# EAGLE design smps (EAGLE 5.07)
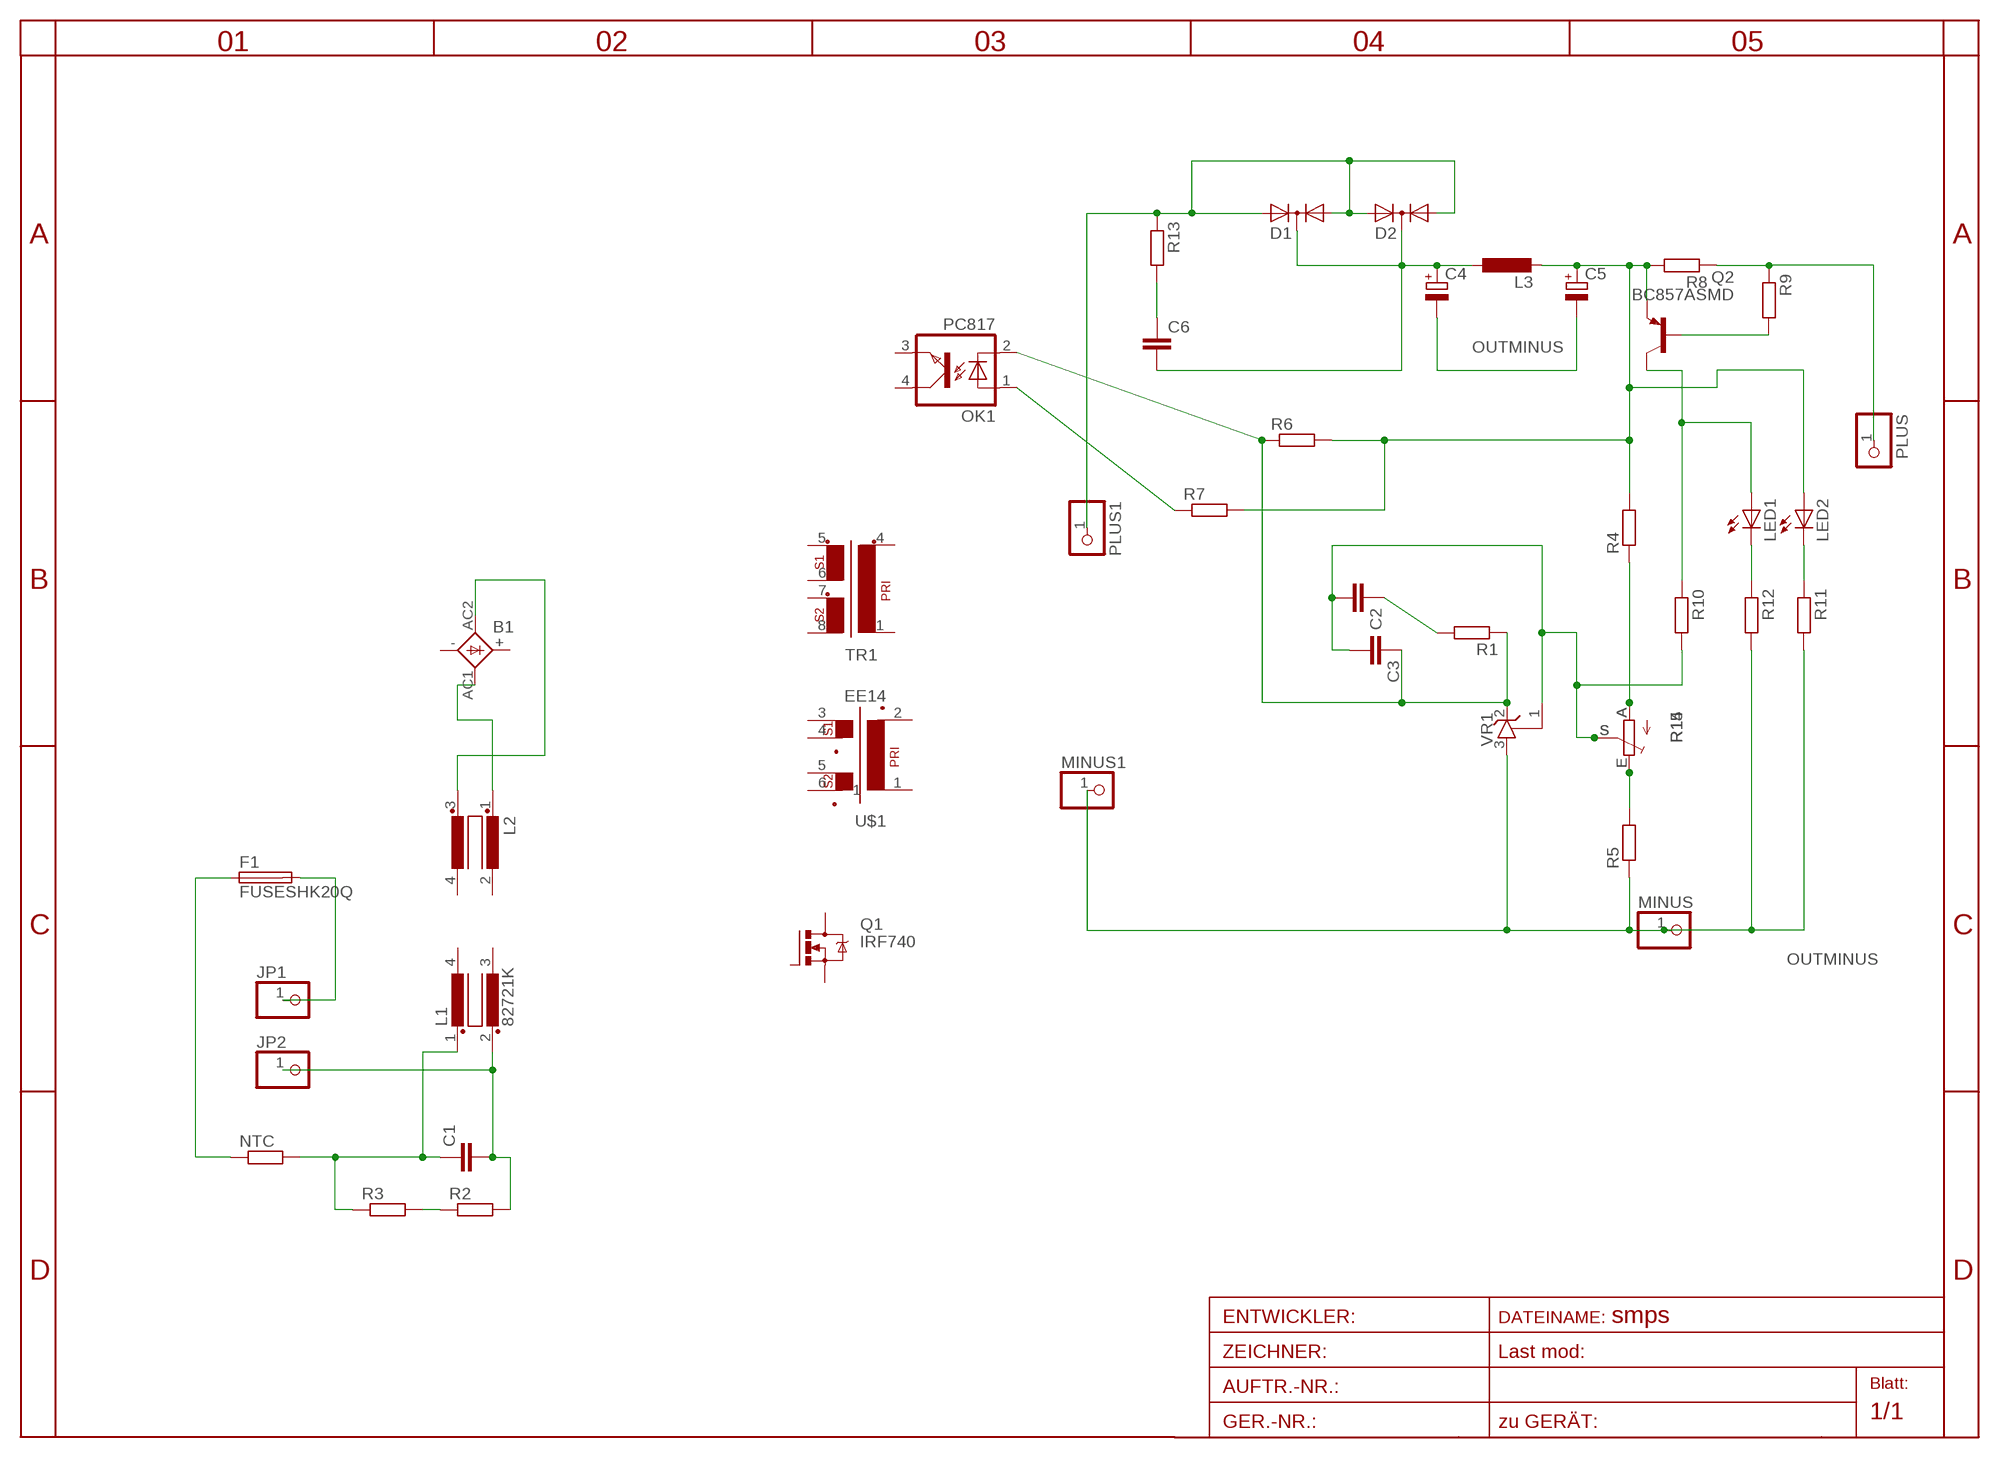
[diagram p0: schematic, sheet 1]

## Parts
B1  KBL  [KBL]
C1  C-EU150-084X183  [C150-084X183]
C2  C-EUC0805  [C0805]
C3  C-EUC0805  [C0805]
C4  CPOL-EUE5-8.5  [E5-8,5]
C5  CPOL-EUE5-8.5  [E5-8,5]
C6  C-EUC0805  [C0805]
D1  DIODE-2AC|CAIW220V  [IW220ABS]
D2  DIODE-2AC|CAIW220V  [IW220ABS]
F1  FUSESHK20Q  [SHK20Q]
JP1  PINHD-1X12MM2  [1X2MM2]
JP2  PINHD-1X12MM2  [1X2MM2]
L1  82721K  [82721K]
L2  R1405VB1  [B1]
L3  L-EU0204/5  [0204/5]
LED1  LED3MM  [LED3MM]
LED2  LED3MM  [LED3MM]
MINUS  PINHD-1X12MM2  [1X2MM2]
MINUS1  PINHD-1X11X0.4  [1X01]
NTC  R-EU_0204/7  [0204/7]
OK1  PC817  [DIL04]
PLUS  PINHD-1X12MM2  [1X2MM2]
PLUS1  PINHD-1X11X0.4  [1X01]
Q1  IRF740  [TO220BV]
Q2  BC857ASMD  [SOT23-BEC]
R1  R-EU_R0805  [R0805]
R2  R-EU_R1206  [R1206]
R3  R-EU_R1206  [R1206]
R4  R-EU_R0805  [R0805]
R5  R-EU_R0805  [R0805]
R6  R-EU_R0805  [R0805]
R7  R-EU_R0805  [R0805]
R8  R-EU_R2010  [R2010]
R9  R-EU_R0805  [R0805]
R10  R-EU_R0805  [R0805]
R11  R-EU_R0805  [R0805]
R12  R-EU_R0805  [R0805]
R13  R-EU_R0805  [R0805]
R14  TRIM_EU-S64W  [S64W]
R15  TRIM_EU-CA6V  [CA6V]
TR1  EE20-2  [EE20-2]
U$1  EE14  [EE14]
VR1  TL431CLPSOT23  [SOT23]

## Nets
A: R4.1 R14.A R15.A
CPLUS: C4.+ C6.2 D1.C D2.C L3.1
E: R5.2 R14.E R15.E
N$1: C1.2 JP2.1 L1.2 R2.2
N$2: C1.1 L1.1 NTC.2 R3.1
N$3: F1.2A JP1.1
N$6: R2.1 R3.2
N$7: B1.AC2(AC1) L2.3
N$8: B1.AC1(AC2) L2.1
N$9: F1.1A NTC.1
N$11: C3.1 OK1.2(C) R1.1 R6.1 VR1.2(C)
N$12: OK1.1(A) R7.1
N$13: C2.1 R1.2
N$14: D1.A1 D1.A2 D2.A1 D2.A2 PLUS1.1 R13.1
N$16: Q2.B R9.2
N$17: LED1.A Q2.C R10.1
N$21: LED1.K(C) R12.1
N$23: LED2.K(C) R11.1
N$27: C6.1 R13.2
OUTMINUS: C4.- C5.- MINUS1.1 MINUS.1 R5.1 R11.2 R12.2 VR1.3(A)
OUTPLUS: PLUS.1 R8.1 R9.1
PLUS2: C5.+ L3.2 LED2.A Q2.E R4.2 R6.2 R7.2 R8.2
S: C2.2 C3.2 R10.2 R14.S R15.S VR1.1(R)
Unconnected: B1.+ B1.- L1.3 L1.4 L2.2 L2.4 OK1.3(EMIT) OK1.4(COL) Q1.D Q1.G Q1.S TR1.1 TR1.4 TR1.5 TR1.6 TR1.7 TR1.8 U$1.1 U$1.2 U$1.3 U$1.4 U$1.5 U$1.6

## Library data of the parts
B1 = rectifier:KBL: DIOTEC RECTIFIER
C1-C3 C6 = rcl:C-EU: CAPACITOR, European symbol
C4 C5 = rcl:CPOL-EU: POLARIZED CAPACITOR, European symbol
D1 D2 = diode:DIODE-2AC|CA: Dual DIODE Anode-Cathode|Cathode-Anode
F1 = fuse:FUSE: Fuse
JP1 JP2 MINUS MINUS1 PLUS PLUS1 = pinhead:PINHD-1X1: PIN HEADER
L1 = inductors:82721K: FILTER
L2 = inductor-nkl:R1405V: Übertrager (verlustarm) bis typ. 400kHz Power transformer (low loss) up to typ. 400kHz
L3 = rcl:L-EU: INDUCTOR, European symbol
LED1 LED2 = led:LED: LED
NTC R1-R13 = rcl:R-EU_: RESISTOR, European symbol
OK1 = optocoupler:PC817: SHARP OPTO COUPLER
Q1 = transistor-power:IRF740: N-CHANNEL MOS FET
Q2 = transistor-pnp:BC857*: PNP Transistror
R14 R15 = pot:TRIM_EU-: POTENTIOMETER
TR1 = trafo:EE20-2: TRANSFORMER 1 primary winding, 2 secondary windings ERA
U$1 = trafo:EE14
VR1 = v-reg:TL431CLP: VOLTAGE REGULATOR

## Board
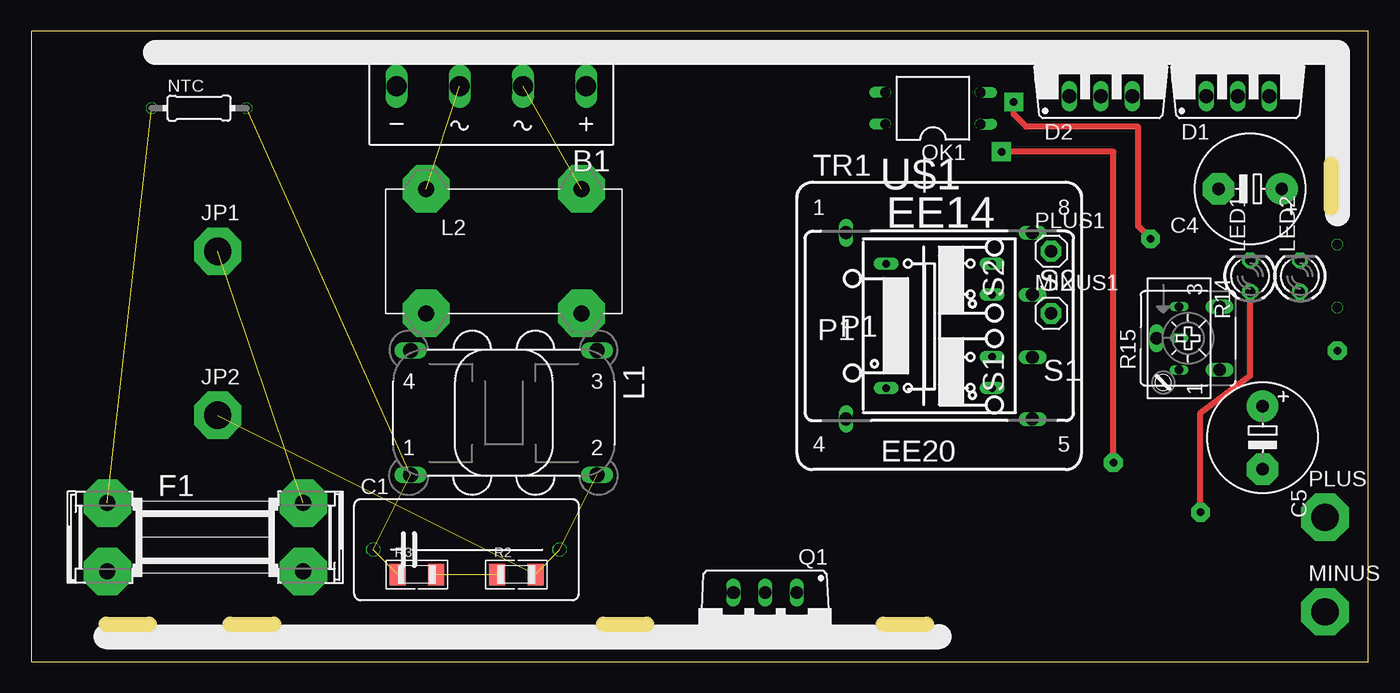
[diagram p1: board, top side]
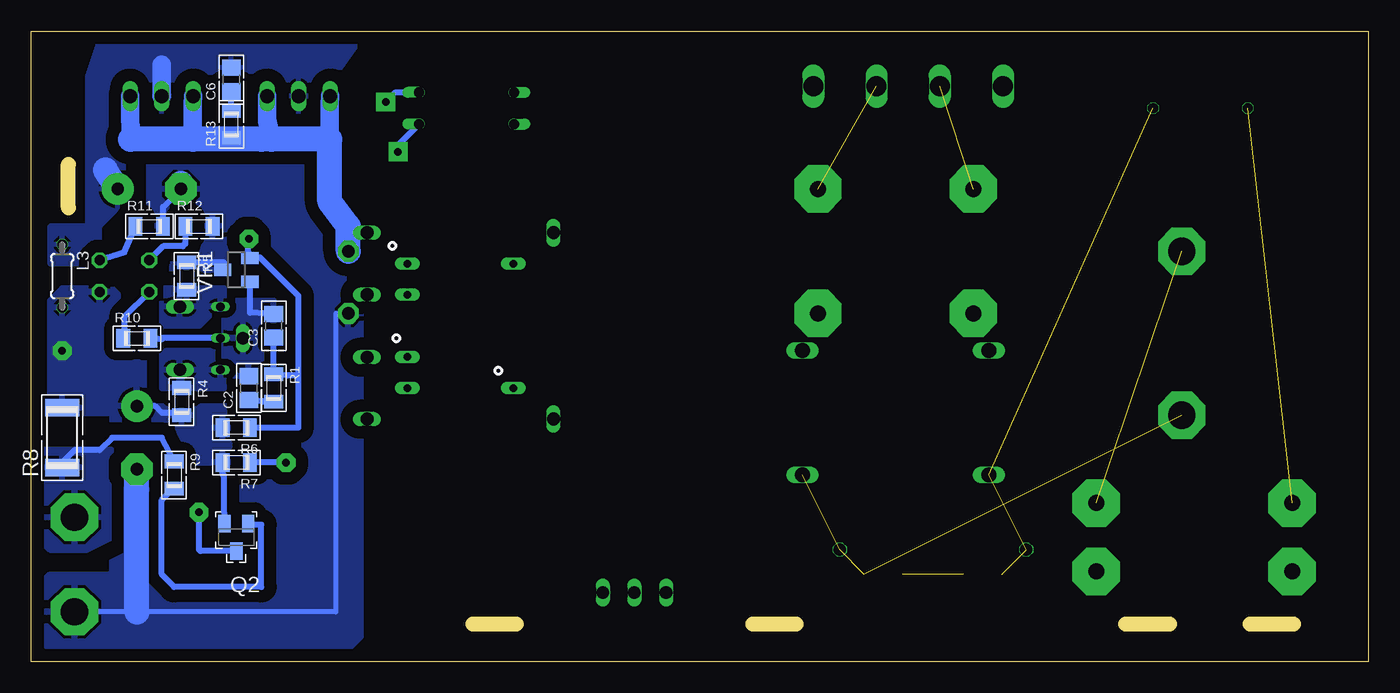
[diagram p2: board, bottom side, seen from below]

Size 107.5 x 50.7 mm. Coordinates in mm from the lower left corner, seen from the top.
Outline: 0,0 107.5,0 107.5,50.7 0,50.7 0,0
Copper layers (1*16): Top 0.035mm / dielectric 1.5mm / Bottom 0.035mm
Design rules "default": minimum track width 10mil, minimum drill 20mil, track to track 8mil, track to pad 8mil, pad to pad 8mil, via to via 8mil, smd to smd 8mil, copper to edge 40mil, drill to drill 8mil, minimum pad ring 1mil, minimum via ring 8mil, stop-mask expansion 4mil, vias tented up to drill 0mil, thermal gap 10mil
Milling: 5 lines

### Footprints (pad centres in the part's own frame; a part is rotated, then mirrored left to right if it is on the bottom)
KBL = drill 1.6 long: + -7.62,-1.27; - 7.62,-1.27; AC1 2.54,-1.27; AC2 -2.54,-1.27
C150-084X183 = drill 1.016 octagon: 1 -7.493,0; 2 7.493,0
C0805 = smd 1.3 x 1.5: 1 -0.95,0; 2 0.95,0
E5-8,5 = drill 1 pad 2.54 round: + -2.54,0 | drill 1 pad 2.54 octagon: - 2.54,0
IW220ABS = drill 1.118 long: A1 -2.54,-2.54; A2 2.54,-2.54; C 0,-2.54
SHK20Q = drill 1.3 pad 3.81 octagon: 1A -7.874,2.75; 1B -7.874,-2.75; 2A 7.874,2.75; 2B 7.874,-2.75
1X2MM2 = drill 2.2 pad 3.81 octagon: 1 0,0
82721K = drill 1.194 long: 1 7.493,5.004; 2 -7.493,5.004; 3 -7.493,-5.004; 4 7.493,-5.004
B1 = drill 1.27 pad 3.81 octagon: 1 -6.25,5; 2 -6.25,-5; 3 6.25,5; 4 6.25,-5
0204/5 = drill 0.813 octagon: 1 -2.54,0; 2 2.54,0
LED3MM = drill 0.8 pad 1.27 octagon: A -1.27,0; K 1.27,0
1X01 = drill 1 pad 1.676 octagon: 1 0,0
0204/7 = drill 0.813 octagon: 1 -3.81,0; 2 3.81,0
DIL04 = drill 0.813 offset: 1 -1.27,-3.81; 2 1.27,-3.81; 3 1.27,3.81; 4 -1.27,3.81
TO220BV = drill 1.016 long: D 0,-2.54; G -2.54,-2.54; S 2.54,-2.54
SOT23-BEC = smd 1 x 1.4: B -0.95,-1.1; C 0,1.1; E 0.95,-1.1
R0805 = smd 1.1 x 1.5: 1 -1.1,0; 2 1.1,0
R1206 = smd 1.3 x 1.7: 1 -1.55,0; 2 1.55,0
R2010 = smd 1.4 x 2.7: 1 -2.4,0; 2 2.4,0
S64W = drill 0.7 long: A 2.54,1.27; E -2.54,1.27; S 0,1.27
CA6V = drill 1.016 long: A -2.54,-2.54; E 2.54,-2.54; S 0,2.54
EE20-2 = drill 1.016 long: 1 -7.493,7.493; 4 -7.493,-7.493; 5 7.493,-7.493; 6 7.493,-2.515; 7 7.493,2.515; 8 7.493,7.493
EE14 = drill 0.6 pad 1 long: 1 4.25,-5; 2 4.25,5; 3 -4.25,5 | drill 0.6 pad 1.016 long: 4 -4.25,2.5; 5 -4.25,-2.5; 6 -4.25,-5
SOT23 = smd 1 x 1.4: 1 -0.95,-1.1; 2 0.95,-1.1; 3 0,1.1

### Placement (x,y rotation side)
B1  37,45 180 top
C1  35,9 0 top
C2  90,22 90 bottom
C3  88,27 90 bottom
C4  98,38 180 top
C5  99,18 270 top
C6  91.4,46.8 90 bottom
D1  97,48 0 top
D2  86,48 0 top
F1  14,10 0 top
JP1  15,33 0 top
JP2  15,19.8 0 top
L1  38,20 180 top
L2  38,33 0 top
L3  105,31 270 bottom
LED1  98,31 90 top
LED2  102,31 90 top
MINUS  104,4 0 top
MINUS1  82,28 0 top
NTC  13.5,44.5 0 top
OK1  72.5,44.5 90 top
PLUS  104,11.6 0 top
PLUS1  82,33 0 top
Q1  59,3 180 top
Q2  91,10 180 bottom
R1  88,22 270 bottom
R2  39,7 0 top
R3  31,7 0 top
R4  95.4,20.9 270 bottom
R5  95,31 270 bottom
R6  91,18.8 180 bottom
R7  91,16 180 bottom
R8  105,18 90 bottom
R9  96,15 270 bottom
R10  99,26 0 bottom
R11  98,35 0 bottom
R12  94,35 0 bottom
R13  91.4,43.2 90 bottom
R14  91,26 270 top
R15  93,26 90 top
TR1  73,27 0 top
U$1  73,27 180 top
VR1  91,31.5 90 bottom

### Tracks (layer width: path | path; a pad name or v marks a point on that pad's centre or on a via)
A
  pour Bottom (isolate 0.5, rank 2): 92,25 97,25 97,24 97,22 92,22
CPLUS
  Bottom 1.5: D1.C 97,48
  Bottom 2: C4.+ 101.54,39.54
  pour Bottom (isolate 1): 81,50 102,50 103,47 103,35 106,35 106,32 103,32 102,33 102,35 100,37 100.1,42.8 86.1,42.8
E
  pour Bottom (isolate 0.5, rank 2): 93,28 92,28 92,30 97,30 97,27 94,27
N$1  (3 unrouted)
N$2  (3 unrouted)
N$3  (1 unrouted)
N$6  (1 unrouted)
N$7  (1 unrouted)
N$8  (1 unrouted)
N$9  (1 unrouted)
N$11  (via drill 0.6 pad 1.5)
  Top 0.5: v79,45 79,44 80,43 89,43 89,35 v90,34
  Bottom 0.5: R6.1 86,18.8 86,23 | 86,23 86.9,23 R1.1 C3.1 | v90,34 90.05,32.95 VR1.2 90.25,32.4 89.1,32.5 86,29.4 86,23 | OK1.2 78.23,45.77 v79,45
N$12  (via drill 0.6 pad 1.5)
  Top 0.5: v87,16 87,41 v78,41
  Bottom 0.5: v87,16 R7.1 | v78,41 78,41.54 OK1.1
N$13
  Bottom 0.5: R1.2 88.85,20.9 C2.1
N$14
  Bottom 0.5: R13.1 89.1,41.9 89,42
  Bottom 1.5: 83.5,42 83.5,44.82 D2.A1 | D2.A2 88.54,43.54 88.2,42 | 94.5,42 94.5,44.9 D1.A1 | D1.A2 99.54,44.54 99.5,42
  Bottom 2: PLUS1.1 82,35 83.5,37 83.5,42 88.2,42 89,42 94.5,42 99.5,42
N$16
  Bottom 0.5: R9.2 96.1,13.9 97,13 97,7 96,6 89,6 89,11 89.95,11 Q2.B
N$17  (via drill 0.6 pad 1.5)
  Top 0.5: v94,12 94,20 98,23 LED1.A
  Bottom 0.5: Q2.C 93.9,8.9 94,9 v94,12 | 100.1,25.9 R10.1 100,26 100,27.73 LED1.A
N$21
  Bottom 0.5: R12.1 95.1,33.6 95.3,33.4 96.87,33.4 LED1.K
N$23
  Bottom 0.5: LED2.K 100,32.9 R11.1
N$27
  Bottom 0.5: R13.2 C6.1
OUTMINUS
  Bottom 0.406: MINUS1.1 83,28 83,4 99,4 MINUS.1
  Bottom 0.5: R11.2 96.9,36.56 C4.- | R5.1 92.1,32.1 92,32 92,32.1 VR1.3
  Bottom 2: C4.- 95.46,38.46 | 99,4 C5.-
  pour Bottom (isolate 1, rank 3): 98,40 84,40 84,33 81,30 81,2 82,1 106,1 107,2 107,6 106,7 101,7 101,15 90,14 89,31 96,31 98,36
OUTPLUS
  Bottom 0.5: R8.1 105,16 104,17 102,17 101,18 97,18 R9.1
  pour Bottom (isolate 1): 107,17 107,10 106,9 103,9 101,10 101,17
PLUS2  (via drill 0.6 pad 1.5)
  Bottom 0.5: C5.+ 97.54,20.54 97,20 96.1,20 R4.2 95.9,20 | Q2.E 91.95,11.95 92,12 92,15 92.1,15 R7.2
  other vias: 105,25
  pour Bottom (isolate 1, rank 4): 101,30 105,30 106,29 106,21 105,20 101,20 101,16 91,16 91,26 100,26 100,29
S
  Bottom 0.5: C3.2 89.9,28.05 VR1.1 | R14.S 97,26 97,25.9 R10.2
  pour Bottom (isolate 0.5): 88,29 92,29 92,23 88,23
